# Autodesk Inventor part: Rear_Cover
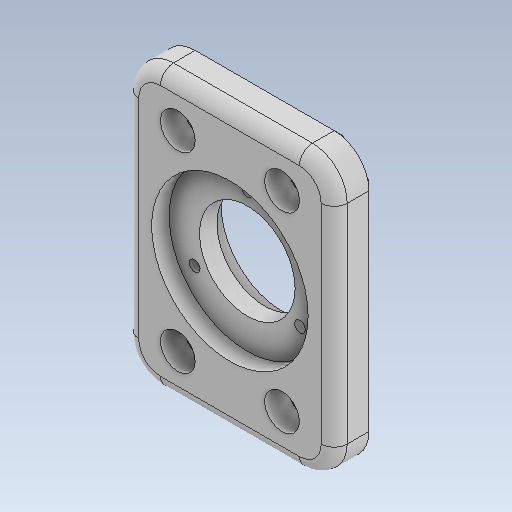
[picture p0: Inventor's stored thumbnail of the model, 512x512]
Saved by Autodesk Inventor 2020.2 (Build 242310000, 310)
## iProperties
Created: 2019-12
Part Number: Rear_Cover
Material: Generic
Document SubType Name: Modeling
Designer: Patrick Everitt
Density: 1 g/cm^3
Appearance: Default
Description: 3 x 3/4 CRS 4.25 LG
Author: Patrick Everitt
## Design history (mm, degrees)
sketch "Sketch1"
  geometry: L1 (-38.1, -38.1)-(-38.1, 38.1); L2 (-25.4, 50.8)-(25.4, 50.8); L3 (38.1, 38.1)-(38.1, -38.1); L4 (25.4, -50.8)-(-25.4, -50.8); C1 r 17.463 at (0, 0); A1 r 12.7 centre (-25.4, 38.1) between (-25.4, 50.8) and (-38.1, 38.1); A2 r 12.7 centre (25.4, 38.1) between (38.1, 38.1) and (25.4, 50.8); A3 r 12.7 centre (25.4, -38.1) between (25.4, -50.8) and (38.1, -38.1); A4 r 12.7 centre (-25.4, -38.1) between (-38.1, -38.1) and (-25.4, -50.8); 4 further points
  constraints: 8 end point, 8 point on circle, 8 tangent, 6 point on line, 5 centre point, 3 equal radius, 2 perpendicular, 1 coincident, 1 parallel, 1 vertical
  dimensions: "d0" = 34.925 diameter of C1; "d1" = 101.6 distance of point (-38.1, -50.8) point (-38.1, 50.8); "d2" = 76.2 distance of point (-38.1, 50.8) point (38.1, 50.8); "d4" = 38.1 distance from line of point (0, 0) L3; "d5" = 50.8 distance from line of point (0, 0) L2; "d6" = 12.7 radius of A1 (derived)
extrude "Extrusion1" new body sketch "Sketch1" distance "d7" = 12.7; taper "d8" = 0 deg
fillet "Fillet1" dims "d12" = 4.7625
sketch "Sketch3"
  geometry: C1 r 28.575 at (0, 0); 1 further point
  constraints: 1 centre point, 1 coincident
  dimensions: "d13" = 57.15 diameter of C1
extrude "Extrusion3" cut sketch "Sketch3" distance "d14" = 6.35; taper "d15" = 0 deg
sketch "Sketch4"
  geometry: C1 r 17.462 at (0, 0) reference; 6 further points
  constraints: 1 coincident, 1 vertical alignment, 1 other
  dimensions: "d16" = 120 deg dimension on point (0, 0) point (0, 22.225) point (19.247, -11.112); "d17" = 120 deg dimension on point (0, 0) point (19.247, -11.112) point (-19.247, -11.113); "d18" = 22.225 distance of point (0, 0) point (0, 22.225); "d19" = 22.225 distance of point (0, 0) point (19.247, -11.112) (= d18); "d20" = 22.225 distance of point (-19.247, -11.113) point (0, 0) (= d18)
hole "Hole1" sketch "Sketch4" at (0, 22.225), (19.247, -11.112), (-19.247, -11.113) diameter "d21" = 3.9624; stored, may be unused: countersink angle "d25" = 82 deg, drill point angle "d27" = 118 deg; dims "d22" = 9.652, "d23" = 9.525, "d24" = 6.35, "d26" = 13.6144
sketch "Sketch5"
  geometry: L1 (-31.75, -34.925)-(-31.75, 34.925); L2 (-33.337, 38.1)-(-33.337, -38.1) reference; L3 (-22.225, -44.45)-(47.625, -44.45); L4 (-22.225, 44.45)-(22.225, 44.45); L5 (31.75, 34.925)-(31.75, -34.925); L6 (22.225, -44.45)-(-31.75, -44.45); L7 (22.225, -44.45)-(31.75, -34.925); L8 (-22.225, -44.45)-(-31.75, -34.925); L9 (-31.75, 34.925)-(-22.225, 44.45); L10 (22.225, 44.45)-(31.75, 34.925); 5 further points
  constraints: 18 end point, 8 point on line, 3 perpendicular, 1 horizontal, 1 parallel
  dimensions: "d28" = 88.9 distance of L6.end point (-31.75, 44.45); "d29" = 90 deg angle of L3 L1 (derived); "d30" = 63.5 distance of point (-31.75, 44.45) point (31.75, 44.45); "d31" = 88.9 distance of point (31.75, 44.45) point (31.75, -44.45); "d32" = 9.525 distance of L6.start point (31.75, -44.45); "d33" = 9.525 distance of L5.end point (31.75, -44.45) (= d32); "d34" = 9.525 distance of L3.start L6.end (= d32); "d35" = 9.525 distance of L1.start L6.end (= d34); "d36" = 9.525 distance of L1.end point (-31.75, 44.45) (= d32); "d37" = 9.525 distance of L4.start point (-31.75, 44.45) (= d36); "d38" = 9.525 distance of L4.end point (31.75, 44.45) (= d32); "d39" = 9.525 distance of L5.start point (31.75, 44.45) (= d38); "d71" = 31.75 distance from line of point (0, 0) L5 (= 0.5 x d30); "d72" = 44.45 distance from line of point (0, 0) L4 (= 0.5 x d31)
extrude "Extrusion4" join sketch "Sketch5" distance "d40" = 6.35; taper "d41" = 0 deg
sketch "Sketch6"
  geometry: C1 r 22.225 at (0, 0); 1 further point
  constraints: 1 centre point, 1 coincident
  dimensions: "d42" = 44.45 diameter of C1
extrude "Extrusion5" cut sketch "Sketch6" distance "d43" = 6.35; taper "d44" = 0 deg
sketch "Sketch7"
  geometry: 5 further points
  dimensions: "d52" = 34.925 vertical distance of point (-19.05, 34.925) point (0, 0); "d53" = 19.05 horizontal distance of point (-19.05, 34.925) point (0, 0); "d54" = 19.05 horizontal distance of point (0, 0) point (19.05, 34.925) (= d53); "d55" = 19.05 horizontal distance of point (-19.05, -34.925) point (0, 0) (= d53); "d56" = 19.05 horizontal distance of point (19.05, -34.925) point (0, 0) (= d53); "d57" = 34.925 vertical distance of point (19.05, 34.925) point (0, 0) (= d52); "d58" = 34.925 vertical distance of point (19.05, -34.925) point (0, 0) (= d52); "d59" = 34.925 vertical distance of point (-19.05, -34.925) point (0, 0) (= d52)
hole "Hole2" sketch "Sketch7" at (-19.05, -34.925), (-19.05, 34.925), (19.05, 34.925), (19.05, -34.925) diameter "d60" = 8.7376; stored, may be unused: countersink angle "d64" = 82 deg, drill point angle "d66" = 118 deg; dims "d61" = 15.875, "d62" = 12.7, "d63" = 8.636, "d65" = 22.9362
body "Solid1"
